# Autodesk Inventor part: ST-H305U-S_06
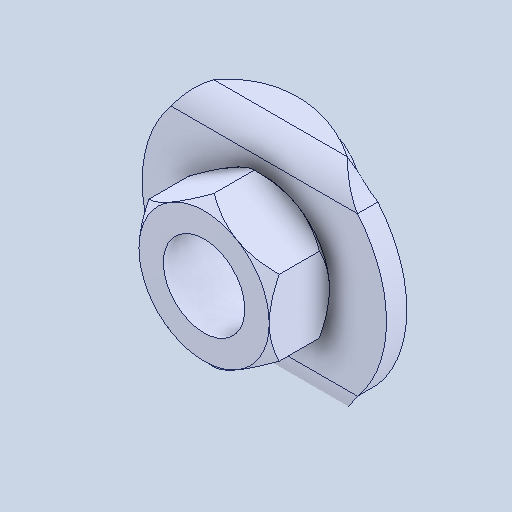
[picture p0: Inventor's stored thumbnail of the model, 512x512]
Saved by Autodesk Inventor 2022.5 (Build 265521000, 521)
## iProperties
Created: 2024-07
Part Number: ST-H305U-S_06
Material: 一般
Document SubType Name: Modeling
Designer: ImaoCorp
Density: 1 g/cm^3
Appearance: 既定
Author: ImaoCorp
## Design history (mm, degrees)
feature "ST-H305U-S_06"
node "ソリッド1"
